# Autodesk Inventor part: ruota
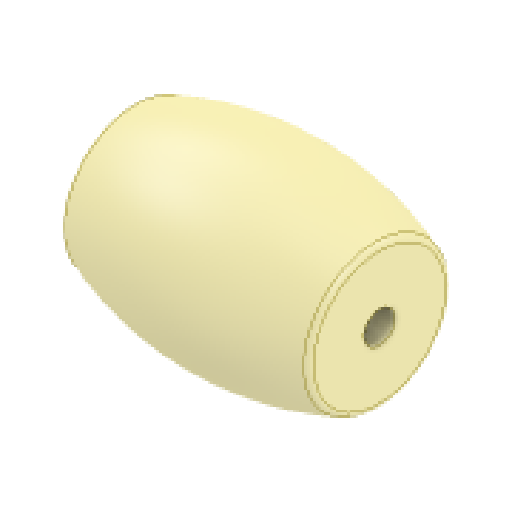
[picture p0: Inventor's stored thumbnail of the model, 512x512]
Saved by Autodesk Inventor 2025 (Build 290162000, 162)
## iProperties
Created: 2025-05
Part Number: ruota
Material: Nylon 6/6
Document SubType Name: Modeling
Designer: R5800u
Density: 1.13 g/cm^3
Appearance: Nylon 6
Author: R5800u
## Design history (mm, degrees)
sketch "Schizzo1"
  geometry: L1 (0, 0)-(-36.77, 36.77); L2 (0, 0)-(-73.48, 0); L3 (-19.6, 48.165)-(-19.6, 0); L4 (0, 0)-(0, 52); L5 (-19.6, 37)-(0, 37); L6 (19.6, 37)-(0, 37); L7 (19.6, 48.165)-(19.6, 0); C1 r 50 at (0, 0); A1 r 52 centre (0, 0) between (-36.77, 36.77) and (-19.6, 48.165); 2 further points
  constraints: 14 end point, 4 point on line, 3 point on circle, 3 symmetric about line, 2 centre point, 2 horizontal, 1 coincident, 1 perpendicular, 1 vertical
  dimensions: "d0" = 100 diameter of C1; "d1" = 2 radial gap between concentric circles of C1 A1; "d3" = 45 deg angle of L2 L1; "d4" = 19.6 distance between parallel lines of L4 L3; "d5" = 37 distance between parallel lines of L2 L5
revolve "Rivoluzione1" sketch "Schizzo1" stored, may be unused: angle "d6" = 90 deg
sketch "Schizzo2"
  geometry: 2 further points
hole "Foro1" sketch "Schizzo2" at (0, 0) diameter "d7" = 5; stored, may be unused: countersink angle "d11" = 90 deg, drill point angle "d13" = 118 deg; dims "d8" = 6, "d9" = 9.4, "d10" = 2, "d12" = 8
fillet "Raccordo1" dims "d14" = 1
node "Solido1"
